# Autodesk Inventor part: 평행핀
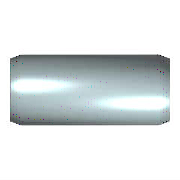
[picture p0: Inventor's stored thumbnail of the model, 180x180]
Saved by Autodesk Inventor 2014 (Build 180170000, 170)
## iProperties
IsCustomPart: 0
Created: 2009-02
Part Number: 평행핀
Material: 강, 연강
Description: 평행 핀
Document SubType Name: Modeling
Standard: KS B 1320
Designer: KYOUNG IL JANG
Standards Organization: KS
Language: ko-KR
Size Designation: B 5 x  20
Categories: <MemberInstance><Categories><Category DisplayName="조임쇠" InternalName="e4da775c-781d-43d5-af7c-5136215cf5a6" Mnemonic="FSTN"><Category DisplayName="핀" InternalNa
Density: 1 g/cm^3
Appearance: 강철
Author: KYOUNG IL JANG
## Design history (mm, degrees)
sketch "스케치"
  geometry: C1 r 2.5 at (0, 0); 1 further point
  constraints: 1 centre point, 1 coincident
  dimensions: "d1" = 5 diameter of C1 (= NND)
extrude "본체" new body sketch "스케치" distance "d2" = 20 (= NLG); taper "d3" = 0 deg
chamfer "스케치2" distance "d8" = 0.8 (= PHH); stored, may be unused: angle "d9" = 15 deg (= FAWI), second distance "d12" = 0.8 (= PHH)
node "작업 평면2"
body "Solid1"
chamfer "모따기1" distance "d4" = 0.8 (= PHH); stored, may be unused: angle "d5" = 15 deg (= FAWI), second distance "d11" = 0.8 (= PHH)
other parameters: "NND" = 5 [user parameter; used in 1 equation term], "NLG" = 20 [user parameter; used in 1 equation term], "PHH" = 0.8 [user parameter; used in 4 equation terms], "FAWI" = 15 deg [user parameter; used in 2 equation terms], "d13" = 0, "d15" = 0, "d16" = 0, "KAH" = 0.63 [user parameter]
